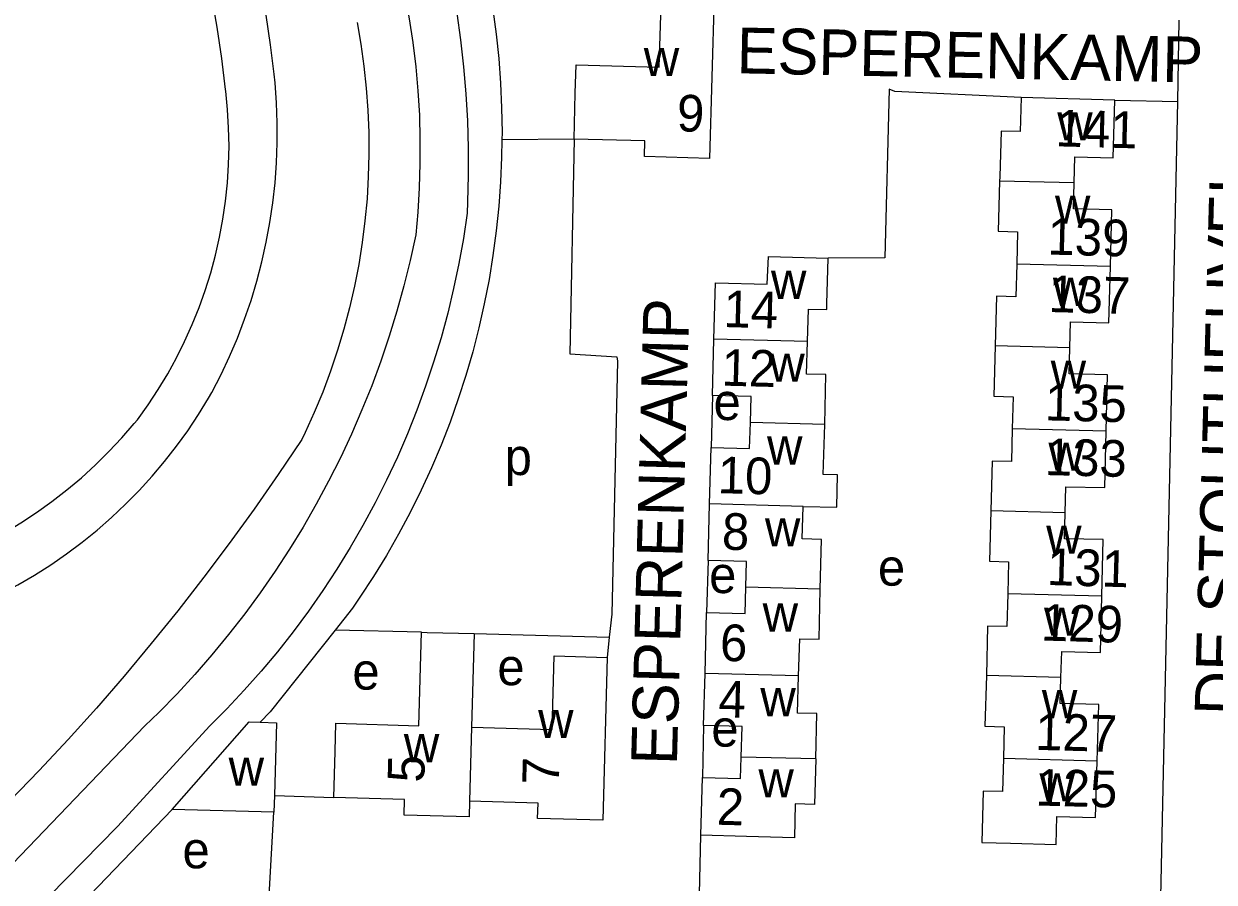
# Model space of a CAD drawing. Extents: x 161936 to 163647, y 386450 to 388633.
# Drawn here: x 162202.6 to 162332.5, y 388304.8 to 388398.4 of the extents above; entities that cross this region are included whole.
import ezdxf

# ---------------------------------------------------------------- set-up
doc = ezdxf.new("R2010")
doc.units = 0
for name, color, linetype in [('BLT_Basislijn', 7, 'Continuous'), ('BLT_Bebouwing', 7, 'Continuous'), ('BLT_Centroide', 7, 'Continuous'), ('BLT_Huisnummer', 7, 'Continuous'), ('BLT_Huisnummer_ tussenligend', 7, 'Continuous'), ('BLT_Onderverdeling_panden', 7, 'Continuous'), ('BLT_Straatnaam', 7, 'Continuous')]:
    doc.layers.add(name, color=color, linetype=linetype)

msp = doc.modelspace()

# ---------------------------------------------------------------- linework, layer by layer
at = {"layer": 'BLT_Basislijn'}
for p, q in [((162328.55, 388389.95), (162328.69, 388398.84)), ((162321.66, 388390.11), (162328.55, 388389.95)), ((162262.65, 388385.85), (162254.78, 388385.78)), ((162277.76, 388357.89), (162277.6, 388352.21)), ((162277.28, 388339.88), (162277.12, 388334.21)), ((162266.76, 388334.03), (162266.49, 388331.52)), ((162246, 388332.04), (162236.59, 388332.29)), ((162266.49, 388331.52), (162266.26, 388329.31)), ((162215.83, 388321.82), (162193.61, 388298.7)), ((162276.79, 388321.88), (162276.67, 388316.2)), ((162276.25, 388299.63), (162276.48, 388309.9))]:
    msp.add_line(p, q, dxfattribs=at)
for points in [[(162229.94, 388392.92), (162229.54, 388396.14), (162229.06, 388399.36), (162228.51, 388402.57), (162227.87, 388405.76), (162227.16, 388408.93), (162226.37, 388412.09), (162225.5, 388415.22), (162224.55, 388418.33), (162223.53, 388421.42), (162222.43, 388424.48), (162221.73, 388426.34)], [(162224.63, 388391.27), (162224.21, 388394.66), (162223.7, 388398.05), (162223.11, 388401.43), (162222.45, 388404.79), (162221.7, 388408.13), (162220.88, 388411.46), (162219.98, 388414.76), (162219.01, 388418.05), (162217.95, 388421.31), (162217.49, 388422.65)], [(162246.64, 388414.02), (162247.44, 388411.17), (162248.16, 388408.31), (162248.8, 388405.42), (162249.37, 388402.52), (162249.86, 388399.6), (162250.27, 388396.67), (162250.59, 388393.74), (162250.84, 388390.79), (162251.01, 388387.84), (162251.1, 388384.88), (162251.11, 388381.93), (162251.04, 388378.97), (162250.99, 388377.76)], [(162242.29, 388409.3), (162243, 388406.76), (162243.63, 388404.18), (162244.18, 388401.6), (162244.66, 388398.99), (162245.05, 388396.38), (162245.37, 388393.75), (162245.61, 388391.11), (162245.77, 388388.47), (162245.84, 388385.82), (162245.84, 388383.18), (162245.76, 388380.53), (162245.6, 388377.89), (162245.37, 388375.4)], [(162253.34, 388402.63), (162253.78, 388399.98), (162254.15, 388397.31), (162254.43, 388394.64), (162254.63, 388391.95), (162254.75, 388389.27), (162254.79, 388386.58), (162254.78, 388385.78)], [(162238.97, 388398.58), (162239.38, 388396.2), (162239.72, 388393.81), (162239.97, 388391.41), (162240.15, 388389), (162240.25, 388386.59), (162240.26, 388384.18), (162240.2, 388381.76), (162240.06, 388379.35), (162239.83, 388376.95), (162239.53, 388374.56), (162239.15, 388372.17), (162238.69, 388369.8), (162238.15, 388367.45), (162237.53, 388365.12), (162236.84, 388362.81), (162236.07, 388360.52), (162235.23, 388358.26), (162234.31, 388356.03), (162233.31, 388353.83), (162232.95, 388353.08)], [(162223.13, 388358.21), (162224.13, 388360.16), (162225.06, 388362.14), (162225.92, 388364.15), (162226.7, 388366.19), (162227.41, 388368.26), (162228.04, 388370.35), (162228.59, 388372.47), (162229.07, 388374.6), (162229.47, 388376.75), (162229.79, 388378.91), (162230.03, 388381.09), (162230.19, 388383.27), (162230.27, 388385.45), (162230.27, 388387.64), (162230.19, 388389.82), (162230.03, 388392), (162229.94, 388392.92)], [(162215, 388355.23), (162216.17, 388356.85), (162217.27, 388358.53), (162218.31, 388360.24), (162219.27, 388361.99), (162220.16, 388363.78), (162220.99, 388365.61), (162221.73, 388367.47), (162222.41, 388369.35), (162223, 388371.26), (162223.52, 388373.19), (162223.97, 388375.15), (162224.33, 388377.11), (162224.62, 388379.09), (162224.82, 388381.09), (162224.95, 388383.08), (162225, 388385.08), (162224.96, 388387.09), (162224.85, 388389.08), (162224.66, 388391.08), (162224.63, 388391.27)], [(162311.43, 388390.38), (162297.67, 388391.05), (162297.02, 388391.29), (162296.56, 388372.91), (162290.37, 388372.88)], [(162326.12, 388287.28), (162326.6, 388299.71), (162328.55, 388389.95)], [(162254.78, 388385.78), (162254.75, 388383.89), (162254.64, 388381.2), (162254.44, 388378.52), (162254.16, 388375.84), (162253.8, 388373.17), (162253.37, 388370.52), (162252.85, 388367.88), (162252.26, 388365.25), (162251.59, 388362.65), (162250.84, 388360.06), (162250.02, 388357.5), (162249.12, 388354.97), (162248.14, 388352.46), (162247.09, 388349.98), (162245.97, 388347.54), (162244.77, 388345.13), (162243.51, 388342.76), (162242.17, 388340.42), (162240.77, 388338.12), (162239.29, 388335.87), (162238.48, 388334.67)], [(162262.65, 388385.85), (162262.18, 388362.44), (162267.31, 388362.11), (162267.38, 388361.64), (162266.76, 388334.03)], [(162250.99, 388377.76), (162250.58, 388375.01), (162250.08, 388372.28), (162249.51, 388369.56), (162248.86, 388366.86), (162248.14, 388364.18), (162247.33, 388361.52), (162246.45, 388358.88), (162245.5, 388356.27), (162244.47, 388353.69), (162243.37, 388351.14), (162242.19, 388348.63), (162240.94, 388346.15), (162239.62, 388343.7), (162238.23, 388341.3), (162236.77, 388338.93), (162235.25, 388336.61), (162233.66, 388334.33), (162232, 388332.1), (162230.28, 388329.92), (162228.5, 388327.79), (162226.66, 388325.71), (162224.75, 388323.69), (162222.9, 388321.82)], [(162245.37, 388375.4), (162244.76, 388372.61), (162244.08, 388369.83), (162243.32, 388367.07), (162242.48, 388364.34), (162241.56, 388361.63), (162240.57, 388358.95), (162239.51, 388356.3), (162238.37, 388353.67), (162237.16, 388351.08), (162235.87, 388348.53), (162234.52, 388346.01), (162233.09, 388343.53), (162231.6, 388341.1), (162230.04, 388338.7), (162228.41, 388336.35), (162226.72, 388334.05), (162224.96, 388331.79), (162223.14, 388329.58), (162221.26, 388327.43), (162219.33, 388325.33), (162217.33, 388323.28), (162215.83, 388321.82)], [(162188.26, 388331.81), (162190.3, 388332.36), (162192.31, 388332.98), (162194.3, 388333.68), (162196.26, 388334.45), (162198.18, 388335.3), (162200.08, 388336.22), (162201.94, 388337.21), (162203.76, 388338.27), (162205.54, 388339.4), (162207.27, 388340.59), (162208.96, 388341.86), (162210.6, 388343.18), (162212.18, 388344.56), (162213.72, 388346.01), (162215.2, 388347.51), (162216.62, 388349.07), (162217.97, 388350.68), (162219.27, 388352.34), (162220.51, 388354.04), (162221.67, 388355.8), (162222.77, 388357.59), (162223.13, 388358.21)], [(162176.97, 388335.8), (162179.03, 388335.96), (162181.08, 388336.21), (162183.12, 388336.53), (162185.15, 388336.94), (162187.16, 388337.42), (162189.15, 388337.98), (162191.12, 388338.61), (162193.06, 388339.32), (162194.97, 388340.11), (162196.85, 388340.97), (162198.69, 388341.9), (162200.5, 388342.9), (162202.27, 388343.97), (162203.99, 388345.11), (162205.67, 388346.32), (162207.31, 388347.58), (162208.89, 388348.91), (162210.42, 388350.3), (162211.89, 388351.75), (162213.31, 388353.26), (162214.66, 388354.82), (162215, 388355.23)], [(162232.95, 388353.08), (162230.38, 388349.25), (162227.73, 388345.47), (162225.02, 388341.73), (162222.25, 388338.04), (162219.41, 388334.4), (162216.51, 388330.81), (162213.55, 388327.27), (162210.53, 388323.78), (162207.44, 388320.35), (162204.3, 388316.96), (162201.1, 388313.64), (162199.25, 388311.77)], [(162238.48, 388334.67), (162236.59, 388332.29)], [(162236.59, 388332.29), (162229.49, 388323.36), (162228.39, 388322.23)], [(162251.75, 388331.9), (162266.49, 388331.52)], [(162222.9, 388321.82), (162212.82, 388310.85), (162192.34, 388290)], [(162229.96, 388314.23), (162236.42, 388314.02)], [(162218.78, 388312.71), (162204.46, 388297.78)], [(162229.38, 388303.32), (162229.9, 388312.43)]]:
    msp.add_lwpolyline(points, dxfattribs=at)
at = {"layer": 'BLT_Bebouwing'}
for p, q in [((162321.66, 388390.11), (162311.43, 388390.38)), ((162277.76, 388357.89), (162277.92, 388364.03)), ((162277.44, 388346.05), (162277.6, 388352.21)), ((162277.28, 388339.88), (162277.44, 388346.05)), ((162276.94, 388327.55), (162277.12, 388334.21)), ((162251.75, 388331.9), (162251.47, 388321.69)), ((162276.79, 388321.88), (162276.94, 388327.55)), ((162276.48, 388309.9), (162276.67, 388316.2)), ((162229.96, 388314.23), (162229.9, 388312.43)), ((162251.25, 388313.61), (162251.2, 388311.9)), ((162229.9, 388312.43), (162218.78, 388312.71))]:
    msp.add_line(p, q, dxfattribs=at)
for points in [[(162262.65, 388385.85), (162262.79, 388390.85), (162262.88, 388393.95), (162271.95, 388393.69), (162272.18, 388401.69), (162272.93, 388401.67), (162276.34, 388401.56)], [(162276.34, 388401.56), (162277.93, 388401.51), (162277.42, 388383.73), (162270.33, 388383.95), (162270.37, 388385.65), (162262.65, 388385.85)], [(162311.43, 388390.38), (162311.34, 388386.68), (162309.24, 388386.73), (162309.1, 388381.74), (162309.09, 388381.28)], [(162317.22, 388381.07), (162317.29, 388383.91), (162321.49, 388383.8), (162321.66, 388390.11)], [(162309.09, 388381.28), (162308.94, 388375.81), (162311.04, 388375.75), (162310.95, 388372.22)], [(162321.18, 388371.96), (162321.34, 388378.12), (162317.14, 388378.23), (162317.22, 388381.07)], [(162277.92, 388364.03), (162278.08, 388370.16), (162283.73, 388370.01), (162283.86, 388373.05), (162290.37, 388372.88)], [(162288.13, 388363.76), (162288.22, 388367.31), (162290.22, 388367.26), (162290.24, 388367.88), (162290.37, 388372.88)], [(162310.95, 388372.22), (162310.85, 388368.66), (162308.75, 388368.72), (162308.61, 388363.28)], [(162316.75, 388363.07), (162316.82, 388365.91), (162321.02, 388365.8), (162321.18, 388371.96)], [(162290, 388354.71), (162290.14, 388360.16), (162288.03, 388360.22), (162288.13, 388363.76)], [(162308.61, 388363.28), (162308.46, 388357.8), (162310.56, 388357.74), (162310.46, 388354.24)], [(162320.71, 388353.97), (162320.87, 388360.12), (162316.68, 388360.23), (162316.75, 388363.07)], [(162281.89, 388354.93), (162281.96, 388357.78), (162277.76, 388357.89)], [(162277.6, 388352.21), (162281.81, 388352.11), (162281.89, 388354.93)], [(162287.65, 388345.78), (162291.31, 388345.68), (162291.4, 388349.22), (162289.85, 388349.26), (162290, 388354.71)], [(162310.46, 388354.24), (162310.37, 388350.66), (162308.27, 388350.71), (162308.12, 388345.29)], [(162316.23, 388345.09), (162316.3, 388347.93), (162320.56, 388347.83), (162320.71, 388353.97)], [(162289.52, 388336.73), (162289.67, 388342.18), (162287.56, 388342.24), (162287.65, 388345.78)], [(162308.12, 388345.29), (162307.97, 388339.8), (162310.07, 388339.74), (162309.98, 388336.23)], [(162320.23, 388335.99), (162320.38, 388342.15), (162316.16, 388342.25), (162316.23, 388345.09)], [(162281.4, 388336.95), (162281.48, 388339.77), (162277.28, 388339.88)], [(162277.12, 388334.21), (162281.33, 388334.09), (162281.4, 388336.95)], [(162287.16, 388327.28), (162287.27, 388331.34), (162289.38, 388331.29), (162289.52, 388336.73)], [(162309.98, 388336.23), (162309.88, 388332.66), (162307.78, 388332.72), (162307.64, 388327.34)], [(162315.78, 388327.11), (162315.86, 388329.95), (162320.08, 388329.82), (162320.23, 388335.99)], [(162236.42, 388314.02), (162236.57, 388319.02), (162236.66, 388322.12), (162245.7, 388321.85), (162246, 388332.04)], [(162246, 388332.04), (162246.64, 388332.02), (162251.75, 388331.9)], [(162266.26, 388329.31), (162265.78, 388311.53), (162258.68, 388311.71), (162258.72, 388313.41), (162251.25, 388313.61)], [(162251.47, 388321.69), (162260.27, 388321.45), (162260.49, 388329.46), (162266.26, 388329.31)], [(162289.03, 388318.22), (162289.16, 388323.17), (162287.05, 388323.22), (162287.16, 388327.28)], [(162307.64, 388327.34), (162307.49, 388321.8), (162309.59, 388321.74), (162309.5, 388318.28)], [(162319.74, 388317.98), (162319.92, 388324.15), (162315.7, 388324.27), (162315.78, 388327.11)], [(162218.78, 388312.71), (162227.2, 388322.27), (162228.39, 388322.23)], [(162228.39, 388322.23), (162230.2, 388322.18), (162229.96, 388314.23)], [(162280.9, 388318.43), (162280.99, 388321.77), (162276.79, 388321.88)], [(162289.03, 388318.22), (162288.9, 388313.27), (162286.79, 388313.33), (162286.69, 388309.63), (162281.48, 388309.76), (162276.48, 388309.9)], [(162276.67, 388316.2), (162280.83, 388316.09), (162280.9, 388318.43)], [(162309.5, 388318.28), (162309.4, 388314.66), (162307.3, 388314.72), (162307.15, 388309.1), (162310.27, 388309.02), (162315.27, 388308.88), (162315.35, 388311.93), (162319.56, 388311.82), (162319.74, 388317.98)], [(162251.2, 388311.9), (162244.1, 388312.1), (162244.15, 388313.8), (162236.42, 388314.02)]]:
    msp.add_lwpolyline(points, dxfattribs=at)
at = {"layer": 'BLT_Onderverdeling_panden'}
for p, q in [((162317.22, 388381.07), (162309.09, 388381.28)), ((162321.18, 388371.96), (162310.95, 388372.22)), ((162288.13, 388363.76), (162277.92, 388364.03)), ((162316.75, 388363.07), (162308.61, 388363.28)), ((162290, 388354.71), (162281.89, 388354.93)), ((162320.71, 388353.97), (162310.46, 388354.24)), ((162287.65, 388345.78), (162277.44, 388346.05)), ((162316.23, 388345.09), (162308.12, 388345.29)), ((162289.52, 388336.73), (162281.4, 388336.95)), ((162320.23, 388335.99), (162309.98, 388336.23)), ((162287.16, 388327.28), (162276.94, 388327.55)), ((162315.78, 388327.11), (162307.64, 388327.34)), ((162251.47, 388321.69), (162251.25, 388313.61)), ((162289.03, 388318.22), (162280.9, 388318.43)), ((162319.74, 388317.98), (162309.5, 388318.28))]:
    msp.add_line(p, q, dxfattribs=at)

# ---------------------------------------------------------------- texts
at = {"layer": 'BLT_Centroide'}
for s, p in [('w', (162270.26, 388392.72)), ('w', (162315.38, 388385.72)), ('w', (162315.13, 388376.62)), ('w', (162284.14, 388368.41)), ('w', (162314.9, 388367.66)), ('w', (162283.96, 388359.38)), ('w', (162314.66, 388358.62)), ('e', (162277.87, 388355.2)), ('w', (162283.71, 388350.34)), ('w', (162314.42, 388349.66)), ('p', (162255.08, 388349.2)), ('w', (162283.48, 388341.41)), ('w', (162314.17, 388340.62)), ('e', (162277.39, 388336.32)), ('e', (162295.81, 388337.13)), ('w', (162283.23, 388332.12)), ('w', (162313.94, 388331.66)), ('e', (162254.28, 388326.27)), ('e', (162238.46, 388325.79)), ('w', (162282.98, 388322.88)), ('w', (162313.7, 388322.66)), ('w', (162258.73, 388320.5)), ('e', (162277.63, 388319.57)), ('w', (162244.08, 388317.86)), ('w', (162224.96, 388315.29)), ('w', (162282.77, 388314.03)), ('w', (162313.44, 388313.59)), ('e', (162219.92, 388306.29))]:
    msp.add_text(s, height=4, dxfattribs=at).set_placement(p)
at = {"layer": 'BLT_Huisnummer'}
for s, rotation, p in [('9', 358.2227, (162273.83, 388386.72)), ('141', 358.5061, (162315.16, 388385.07)), ('137', 358.5298, (162314.38, 388366.99)), ('14', 358.4849, (162278.92, 388365.35)), ('133', 358.6016, (162314, 388349.2)), ('10', 358.485, (162278.29, 388347.23)), ('129', 358.347, (162313.57, 388331.15)), ('6', 358.4806, (162278.54, 388328.93)), ('5', 88.4404, (162246.3, 388315.62)), ('7', 88.4536, (162260.99, 388315.37)), ('125', 358.4642, (162312.96, 388313.15)), ('2', 358.4874, (162278.18, 388311.05))]:
    msp.add_text(s, height=4, rotation=rotation, dxfattribs=at).set_placement(p)
at = {"layer": 'BLT_Huisnummer_ tussenligend'}
for s, rotation, p in [('139', 358.5298, (162314.28, 388373.26)), ('12', 358.485, (162278.71, 388358.96)), ('135', 358.6016, (162314, 388355.17)), ('8', 358.4806, (162278.75, 388341.07)), ('131', 358.347, (162314.22, 388337.21)), ('4', 358.4874, (162278.37, 388322.79)), ('127', 358.4642, (162312.94, 388319.22))]:
    msp.add_text(s, height=4, rotation=rotation, dxfattribs=at).set_placement(p)
at = {"layer": 'BLT_Straatnaam'}
for s, height, rotation, p in [('ESPERENKAMP', 5, 358.8302, (162280.36, 388393.04)), ('DE STOUTHEUVEL', 5, 88.401, (162335.36, 388322.93)), ('ESPERENKAMP', 4.9999, 88.4526, (162273.87, 388317.52))]:
    msp.add_text(s, height=height, rotation=rotation, dxfattribs=at).set_placement(p)

doc.saveas('drawing.dxf')
